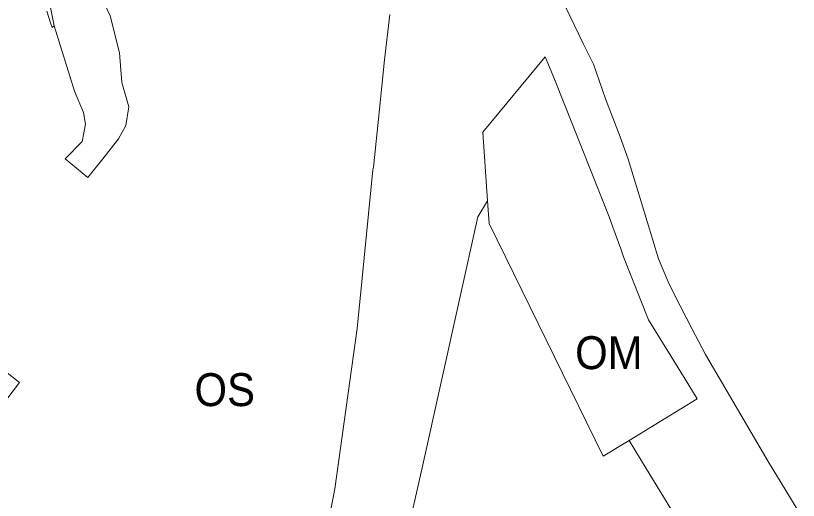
# Model space of a CAD drawing. Extents: x -650451 to -642268, y -1075216 to -1066610.
# Drawn here: x -646629.3 to -646344.3, y -1071875.1 to -1071698.5 of the extents above; entities that cross this region are included whole.
import ezdxf

# ---------------------------------------------------------------- set-up
doc = ezdxf.new("R2010")
doc.units = 0
doc.header["$LTSCALE"] = 4.8
for name, color, linetype, lineweight in [('11', 7, 'Continuous', 13), ('12', 7, 'Continuous', 13), ('15', 7, 'Continuous', 13), ('24', 7, 'Continuous', 13), ('45', 7, 'Continuous', 13), ('9', 7, 'Continuous', 13)]:
    doc.layers.add(name, color=color, linetype=linetype, lineweight=lineweight)
doc.layers.add('62', color=7, linetype='Continuous')

msp = doc.modelspace()

# ---------------------------------------------------------------- linework, layer by layer
at = {"layer": '11'}
msp.add_lwpolyline([(-646305.73, -1071933.35), (-646314.39, -1071923.77), (-646331.27, -1071900.42), (-646355.29, -1071860.97), (-646378.11, -1071821.99), (-646382.96, -1071812.65), (-646387.39, -1071804.2), (-646391.38, -1071796.27), (-646395.23, -1071787.02), (-646401.48, -1071766.63), (-646406.33, -1071750.8), (-646409.27, -1071742.67), (-646414.59, -1071728.79), (-646418.89, -1071716.1), (-646422.74, -1071708.61), (-646435.53, -1071681.73)], dxfattribs=at)
at = {"layer": '12'}
for points in [[(-646457.52, -1071765.98), (-646459.25, -1071740.89), (-646436.46, -1071713.46), (-646433.18, -1071721.61), (-646413.21, -1071771.82), (-646411.83, -1071775.59), (-646408.98, -1071783.42), (-646408, -1071786.35), (-646398.85, -1071809.29), (-646385.58, -1071830.98), (-646381.21, -1071838.12), (-646387.17, -1071841.76), (-646405.99, -1071853.26)], [(-646405.99, -1071853.26), (-646415.46, -1071859.05), (-646456.96, -1071774.2), (-646457.52, -1071765.98)]]:
    msp.add_lwpolyline(points, dxfattribs=at)
at = {"layer": '15'}
for points in [[(-646599.91, -1071676.7), (-646600.39, -1071661.57), (-646598.02, -1071656.99), (-646597.62, -1071651.17), (-646603.36, -1071645.9), (-646607.42, -1071644.31), (-646612.06, -1071644.82), (-646619.02, -1071683.21), (-646615.23, -1071702.21)], [(-646615.23, -1071702.21), (-646616.06, -1071702.77), (-646616.6, -1071701.04), (-646617.9, -1071696.83)], [(-646643.11, -1071814.6), (-646645.26, -1071818.72), (-646627.89, -1071832.14), (-646664.304, -1071879.909), (-646661.359, -1071893.179), (-646644.617, -1071922.541), (-646598.577, -1071960.596), (-646563.366, -1071989.538)]]:
    msp.add_lwpolyline(points, dxfattribs=at)
at = {"layer": '24'}
for points in [[(-646435.53, -1071681.73), (-646422.74, -1071708.61), (-646418.89, -1071716.1), (-646414.59, -1071728.79), (-646409.27, -1071742.67), (-646406.33, -1071750.8), (-646401.48, -1071766.63), (-646395.23, -1071787.02), (-646391.38, -1071796.27), (-646387.39, -1071804.2), (-646382.96, -1071812.65), (-646378.11, -1071821.99), (-646355.29, -1071860.97), (-646331.27, -1071900.42), (-646314.39, -1071923.77), (-646305.73, -1071933.35)], [(-646563.366, -1071989.538), (-646560.5, -1071985.93), (-646549.35, -1071970.07), (-646542.34, -1071958.23), (-646532.74, -1071938.42), (-646526.36, -1071922.76), (-646520.43, -1071906.43), (-646516.21, -1071888.59), (-646514.6, -1071878.48), (-646513.09, -1071870.85), (-646504.93, -1071812.52), (-646503.16, -1071794.13), (-646499.22, -1071754.7), (-646498.98, -1071753.64), (-646496.94, -1071733.76), (-646495.05, -1071714.52), (-646493.07, -1071698.02)], [(-646405.99, -1071853.26), (-646387.17, -1071841.76), (-646381.21, -1071838.12), (-646385.58, -1071830.98), (-646398.85, -1071809.29), (-646408, -1071786.35), (-646408.98, -1071783.42), (-646411.83, -1071775.59), (-646413.21, -1071771.82), (-646433.18, -1071721.61), (-646436.46, -1071713.46), (-646459.25, -1071740.89), (-646457.52, -1071765.98)], [(-646457.52, -1071765.98), (-646461.09, -1071771.76), (-646481.02, -1071862.13), (-646489.34, -1071898.61), (-646499.741, -1071922.455), (-646501.876, -1071927.351), (-646508.83, -1071943.3), (-646510.36, -1071945.61)], [(-646391.83, -1071879.32), (-646390.732, -1071878.171), (-646399.72, -1071863.5), (-646405.99, -1071853.26)]]:
    msp.add_lwpolyline(points, dxfattribs=at)
at = {"layer": '45'}
for points in [[(-646615.23, -1071702.21), (-646619.02, -1071683.21), (-646612.06, -1071644.82), (-646607.42, -1071644.31), (-646603.36, -1071645.9), (-646597.62, -1071651.17), (-646598.02, -1071656.99), (-646600.39, -1071661.57), (-646599.91, -1071676.7)], [(-646599.91, -1071676.7), (-646597.99, -1071691.68), (-646594.93, -1071698.58), (-646591.55, -1071712), (-646590.67, -1071722.85), (-646588.13, -1071731.67), (-646589.23, -1071738.51), (-646591.81, -1071743.29), (-646597.62, -1071750.65), (-646603.02, -1071757.41), (-646611.33, -1071750.69), (-646605.08, -1071744.33), (-646603.88, -1071738.02), (-646604.63, -1071733.78), (-646607.94, -1071725.97), (-646615.23, -1071702.21)]]:
    msp.add_lwpolyline(points, dxfattribs=at)
at = {"layer": '9'}
for points in [[(-646615.23, -1071702.21), (-646607.94, -1071725.97), (-646604.63, -1071733.78), (-646603.88, -1071738.02), (-646605.08, -1071744.33), (-646611.33, -1071750.69), (-646603.02, -1071757.41), (-646597.62, -1071750.65), (-646591.81, -1071743.29), (-646589.23, -1071738.51), (-646588.13, -1071731.67), (-646590.67, -1071722.85), (-646591.55, -1071712), (-646594.93, -1071698.58), (-646597.99, -1071691.68), (-646599.91, -1071676.7)], [(-646617.9, -1071696.83), (-646616.6, -1071701.04), (-646616.06, -1071702.77), (-646615.23, -1071702.21)], [(-646493.07, -1071698.02), (-646495.05, -1071714.52), (-646496.94, -1071733.76), (-646498.98, -1071753.64), (-646499.22, -1071754.7), (-646503.16, -1071794.13), (-646504.93, -1071812.52), (-646513.09, -1071870.85), (-646514.6, -1071878.48), (-646516.21, -1071888.59), (-646520.43, -1071906.43), (-646526.36, -1071922.76), (-646532.74, -1071938.42), (-646542.34, -1071958.23), (-646549.35, -1071970.07), (-646560.5, -1071985.93), (-646563.366, -1071989.538)], [(-646563.366, -1071989.538), (-646598.577, -1071960.596), (-646644.617, -1071922.541), (-646661.359, -1071893.179), (-646664.304, -1071879.909), (-646627.89, -1071832.14), (-646645.26, -1071818.72), (-646643.11, -1071814.6)]]:
    msp.add_lwpolyline(points, dxfattribs=at)

# ---------------------------------------------------------------- texts
at = {"layer": '62', "width": 0.95}
for s, p in [('OM', (-646425.601, -1071827.276)), ('OS', (-646564.195, -1071840.752))]:
    msp.add_text(s, height=12, dxfattribs=at).set_placement(p)

doc.saveas('drawing.dxf')
